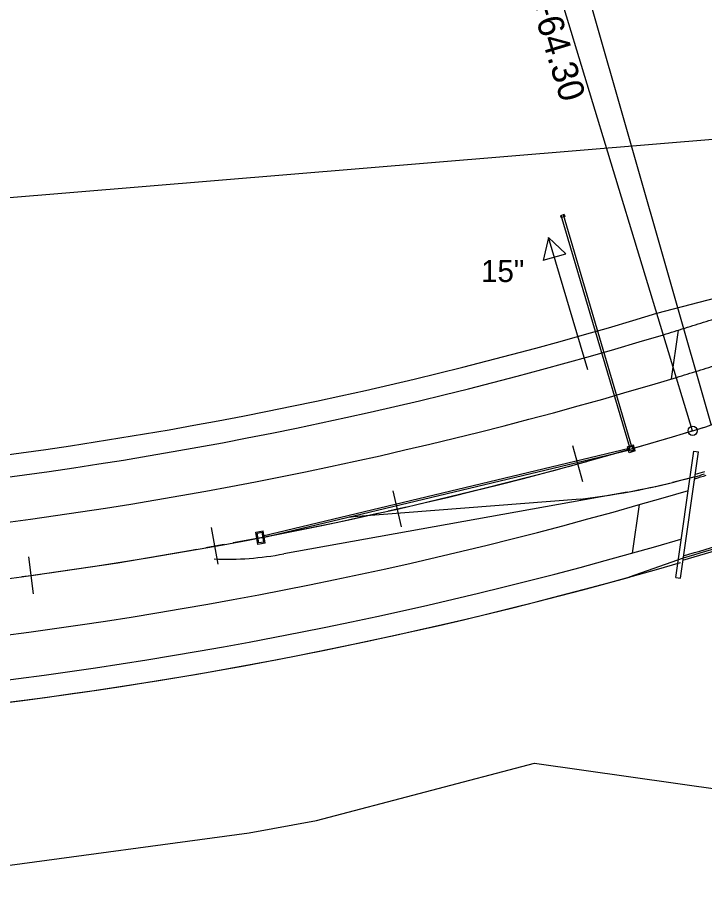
# Model space of a CAD drawing. Extents: x 0 to 3400, y 0 to 2200.
# Drawn here: x 1652.4 to 2021.7, y 265.3 to 731 of the extents above; entities that cross this region are included whole.
import ezdxf

# ---------------------------------------------------------------- set-up
doc = ezdxf.new("R2010")
doc.units = 0
for name, color, linetype in [('Default', 7, 'Continuous'), ('DR_X_Culvert', 7, 'Continuous'), ('DR_X_Text', 7, 'Continuous'), ('GE_P_CL_100', 7, 'Continuous'), ('PV_P_EOP', 7, 'Continuous'), ('RD_X_GR_Lt', 7, 'Continuous'), ('RD_X_GR_Rt', 7, 'Continuous'), ('RW_X_Esmt_LA', 7, 'Continuous'), ('SC_Scratch10', 7, 'Continuous'), ('SH_Data', 7, 'Continuous')]:
    doc.layers.add(name, color=color, linetype=linetype)

msp = doc.modelspace()

# ---------------------------------------------------------------- linework, layer by layer
at = {"layer": 'Default'}
for p, q in [((2003.92, 536.66), (2007.66, 562.89)), ((1956.28, 481.35), (1950.92, 500.62)), ((2006.3, 429.9), (2015.97, 497.77)), ((2008.78, 429.55), (2018.45, 497.42)), ((2015.97, 497.77), (2018.45, 497.42)), ((1858.77, 457.04), (1854.37, 476.55)), ((1955.06, 472.01), (1830.68, 462.31)), ((1955.06, 472.01), (1830.68, 462.31)), ((1982.92, 443.05), (1986.63, 469.05)), ((1830.68, 462.31), (1830.68, 462.31)), ((1760.38, 437.01), (1756.79, 456.69)), ((1661.12, 421.1), (1658.58, 440.94)), ((1981.32, 430.15), (2010.32, 440.54)), ((1981.32, 430.15), (2010.32, 440.54)), ((2006.3, 429.9), (2008.78, 429.55))]:
    msp.add_line(p, q, dxfattribs=at)
for points in [[(1963.23, 493.66), (1979.89, 498.3), (2004.37, 505.47), (2010.43, 507.31), (2013.41, 508.21), (2016.38, 509.12), (2019.35, 510.03), (2022.32, 510.95), (2025.29, 511.87), (2028.26, 512.8), (2031.23, 513.72), (2034.19, 514.66), (2037.16, 515.59), (2039.91, 516.47)], [(1948.78, 489.64), (1953.6, 490.98)], [(1953.6, 490.98), (1958.41, 492.32)], [(1866.32, 469.03), (1902.6, 477.65), (1941.34, 487.57), (1943.96, 488.3)], [(1851.69, 465.69), (1856.57, 466.79)], [(1856.57, 466.79), (1861.45, 467.89)], [(1768.42, 448.65), (1785.28, 451.73), (1824.58, 459.57), (1846.82, 464.59)], [(1831.84, 462.4), (1830.68, 462.31)], [(1758.59, 446.85), (1763.5, 447.75)], [(1669.77, 432.34), (1706.47, 437.84), (1745.97, 444.54), (1748.75, 445.05)], [(1753.67, 445.95), (1758.59, 446.85)], [(1654.89, 430.38), (1659.85, 431.02)], [(1659.85, 431.02), (1664.81, 431.65)]]:
    msp.add_lwpolyline(points, dxfattribs=at)
for centre, radius, start, end in [((1349.37, 2701.71), 2225.83, 242.78381, 286.891), ((1349.37, 2701.71), 2225.83, 242.78381, 286.891), ((1349.37, 2701.71), 2291.83, 242.78381, 286.60667), ((1349.37, 2701.71), 2316.83, 286.73456, 286.891), ((1348.85, 2701.49), 2315.83, 286.75999, 286.891), ((1349.37, 2701.71), 2314.66, 286.75999, 286.891), ((1905.03, 887.13), 418.13, 276.8717, 285.4688), ((1905.03, 887.13), 418.13, 276.8717, 285.4688), ((1349.95, 2701.92), 2355.83, 286.27879, 286.891), ((1349.37, 2701.71), 2354.83, 286.3024, 286.891), ((1349.37, 2701.71), 2357, 286.27879, 286.891), ((1349.37, 2701.71), 2357.83, 265.42229, 285.54661), ((1349.37, 2701.71), 2357.83, 265.42229, 285.54661)]:
    msp.add_arc(centre, radius, start, end, dxfattribs=at)
msp.add_spline([(2010.43, 507.31), (2016.38, 509.12), (2022.32, 510.95), (2028.26, 512.8), (2034.19, 514.66), (2040.12, 516.53), (2046.04, 518.42), (2051.96, 520.33), (2057.87, 522.24), (2063.77, 524.17), (2069.67, 526.12), (2075.56, 528.08), (2081.45, 530.05), (2087.34, 532.03), (2093.22, 534.03), (2099.09, 536.03), (2104.95, 538.05), (2110.82, 540.08), (2116.67, 542.13), (2122.53, 544.18), (2128.37, 546.24), (2134.22, 548.32), (2140.05, 550.4), (2140.1, 550.42)], degree=3, dxfattribs=at)
at = {"layer": 'DR_X_Culvert'}
for p, q in [((1946.25, 624.96), (1944.25, 624.37)), ((1944.25, 624.37), (1944.53, 623.41)), ((1981.47, 499.81), (1944.65, 624.49)), ((1982.67, 500.16), (1945.85, 624.84)), ((1946.25, 624.96), (1946.53, 624)), ((1946.53, 624), (1944.53, 623.41)), ((1981.24, 499.28), (1784.26, 452.13)), ((1983.48, 501.1), (1980.28, 500.15)), ((1981.23, 496.96), (1980.28, 500.15)), ((1983.03, 500.27), (1981.11, 499.7)), ((1981.68, 497.79), (1981.11, 499.7)), ((1981.4, 498.75), (1981.4, 498.75)), ((1982.36, 499.03), (1982.36, 499.03)), ((1982.37, 499), (1982.37, 499)), ((1982.53, 499.08), (1982.53, 499.08)), ((1983.6, 498.35), (1983.03, 500.27)), ((1984.43, 497.9), (1983.48, 501.1)), ((1981.52, 498.32), (1784.44, 451.14)), ((1984.43, 497.9), (1981.23, 496.96)), ((1983.6, 498.35), (1981.68, 497.79)), ((1780.49, 454.24), (1784.42, 454.96)), ((1781.69, 447.69), (1780.49, 454.24)), ((1781.26, 453.7), (1783.89, 454.18)), ((1782.22, 448.46), (1781.26, 453.7)), ((1784.85, 448.95), (1783.89, 454.18)), ((1785.62, 448.41), (1784.42, 454.96)), ((1785.62, 448.41), (1781.69, 447.69)), ((1784.85, 448.95), (1782.22, 448.46)), ((1783.06, 451.32), (1783.06, 451.32)), ((1785.02, 451.68), (1785.02, 451.68)), ((1785.02, 451.68), (1785.02, 451.68))]:
    msp.add_line(p, q, dxfattribs=at)
at = {"layer": 'DR_X_Text'}
for p, q in [((1937.87, 612.7), (1934.89, 600.34)), ((1947.09, 603.94), (1937.87, 612.7)), ((1958.9, 541.48), (1937.87, 612.7)), ((1934.92, 600.49), (1947.09, 603.94))]:
    msp.add_line(p, q, dxfattribs=at)
at = {"layer": 'PV_P_EOP'}
for radius, end in [(2237.83, 286.891), (2261.83, 286.891), (2321.83, 286.60667), (2345.83, 286.33136)]:
    msp.add_arc((1349.37, 2701.71), radius, 242.78381, end, dxfattribs=at)
for points in [[(1999.57, 560.42), (2005.32, 562.18), (2011.07, 563.95), (2016.81, 565.73), (2022.55, 567.53), (2028.29, 569.35), (2034.03, 571.18), (2034.11, 571.2)], [(2006.55, 537.46), (2012.36, 539.23), (2018.16, 541.02), (2023.97, 542.82), (2029.77, 544.64), (2030.19, 544.77)]]:
    msp.add_spline(points, degree=3, dxfattribs=at)
at = {"layer": 'RD_X_GR_Lt'}
msp.add_line((1996.09, 571.91), (2038.07, 582.95), dxfattribs=at)
msp.add_arc((1349.37, 2701.71), 2225.83, 242.78381, 286.891, dxfattribs=at)
at = {"layer": 'RD_X_GR_Rt'}
for p, q in [((2016.65, 484.04), (2004.52, 481.01)), ((1980.09, 475.75), (1795.54, 442.59))]:
    msp.add_line(p, q, dxfattribs=at)
for centre, radius, start, end in [((1910.1, 859.69), 390.27, 280.3308, 284.0011), ((1765.49, 598.22), 158.5, 267.3743, 280.9297), ((1349.37, 2701.71), 2357.83, 265.4225, 286.24125)]:
    msp.add_arc(centre, radius, start, end, dxfattribs=at)
at = {"layer": 'RW_X_Esmt_LA'}
for p, q in [((1405.26, 614.11), (2051.81, 667.67)), ((1813.13, 299.23), (1930.33, 330)), ((1930.33, 330), (2062.52, 311.23)), ((1777.05, 292.55), (1813.13, 299.23)), ((1574.68, 265.28), (1777.05, 292.55))]:
    msp.add_line(p, q, dxfattribs=at)
at = {"layer": 'SC_Scratch10'}
for p, q in [((1953.6, 490.98), (1953.6, 490.98)), ((1856.57, 466.79), (1856.57, 466.79)), ((1758.59, 446.85), (1758.59, 446.85)), ((2008.81, 437.98), (2008.81, 437.98)), ((1996.8, 434.51), (1996.8, 434.51)), ((1659.85, 431.02), (1659.85, 431.02))]:
    msp.add_line(p, q, dxfattribs=at)
at = {"layer": 'SH_Data'}
for p, q in [((1917.37, 889.49), (2025.25, 511.86)), ((2015.27, 508.75), (1908.81, 859.35))]:
    msp.add_line(p, q, dxfattribs=at)
msp.add_circle((2015.27, 508.75), 2.5, dxfattribs=at)

# ---------------------------------------------------------------- texts
at = {"layer": 'DR_X_Text'}
msp.add_text('15"', height=11.86, dxfattribs=at).set_placement((1901.56, 588.72))
at = {"layer": 'GE_P_CL_100'}
msp.add_text('C.S. STA. 199+64.30', height=14, rotation=286.8911, dxfattribs=at).set_placement((1893.1, 854.5))

doc.saveas('drawing.dxf')
